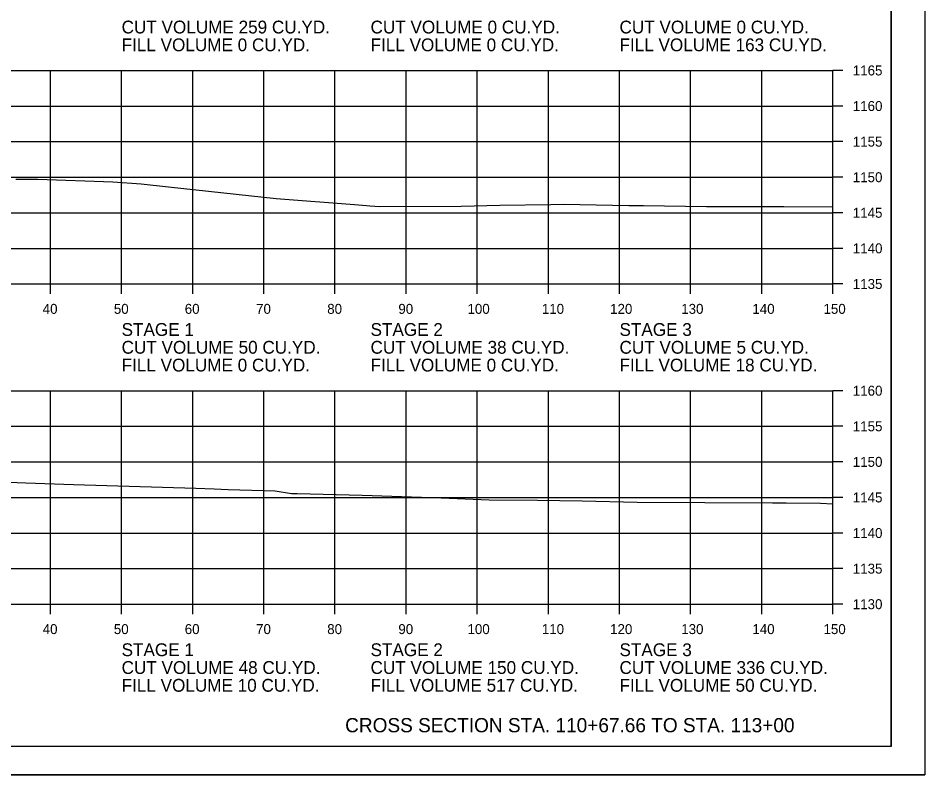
# Model space of a CAD drawing. Extents: x 1368971 to 1374497, y 378717 to 381839.
# Drawn here: x 1371088.2 to 1371215.6, y 379783.8 to 379890.1 of the extents above; entities that cross this region are included whole.
import ezdxf

# ---------------------------------------------------------------- set-up
doc = ezdxf.new("R2010")
doc.units = 0
for name, color, linetype in [('R_Axis', 7, 'Continuous'), ('R_Axis Annot', 7, 'Continuous'), ('R_Border', 7, 'Continuous'), ('R_Draft', 7, 'Continuous'), ('R_Exist Surface', 7, 'Continuous'), ('R_Grid', 7, 'Continuous'), ('R_No Plot', 7, 'Continuous')]:
    doc.layers.add(name, color=color, linetype=linetype)

msp = doc.modelspace()

# ---------------------------------------------------------------- linework, layer by layer
at = {"layer": 'R_Axis'}
for p, q in [((1371202.71, 379852.75), (1371202.71, 379882.75)), ((1371204.11, 379882.75), (1371202.71, 379882.75)), ((1371204.11, 379877.75), (1371202.71, 379877.75)), ((1371204.11, 379872.75), (1371202.71, 379872.75)), ((1371204.11, 379867.75), (1371202.71, 379867.75)), ((1371204.11, 379862.75), (1371202.71, 379862.75)), ((1371204.11, 379857.75), (1371202.71, 379857.75)), ((1370902.71, 379852.75), (1371202.71, 379852.75)), ((1371092.71, 379851.35), (1371092.71, 379852.75)), ((1371102.71, 379851.35), (1371102.71, 379852.75)), ((1371112.71, 379851.35), (1371112.71, 379852.75)), ((1371122.71, 379851.35), (1371122.71, 379852.75)), ((1371132.71, 379851.35), (1371132.71, 379852.75)), ((1371142.71, 379851.35), (1371142.71, 379852.75)), ((1371152.71, 379851.35), (1371152.71, 379852.75)), ((1371162.71, 379851.35), (1371162.71, 379852.75)), ((1371172.71, 379851.35), (1371172.71, 379852.75)), ((1371182.71, 379851.35), (1371182.71, 379852.75)), ((1371192.71, 379851.35), (1371192.71, 379852.75)), ((1371202.71, 379851.35), (1371202.71, 379852.75)), ((1371204.11, 379852.75), (1371202.71, 379852.75)), ((1371202.71, 379807.75), (1371202.71, 379837.75)), ((1371204.11, 379837.75), (1371202.71, 379837.75)), ((1371204.11, 379832.75), (1371202.71, 379832.75)), ((1371204.11, 379827.75), (1371202.71, 379827.75)), ((1371204.11, 379822.75), (1371202.71, 379822.75)), ((1371204.11, 379817.75), (1371202.71, 379817.75)), ((1371204.11, 379812.75), (1371202.71, 379812.75)), ((1370902.71, 379807.75), (1371202.71, 379807.75)), ((1371092.71, 379806.35), (1371092.71, 379807.75)), ((1371102.71, 379806.35), (1371102.71, 379807.75)), ((1371112.71, 379806.35), (1371112.71, 379807.75)), ((1371122.71, 379806.35), (1371122.71, 379807.75)), ((1371132.71, 379806.35), (1371132.71, 379807.75)), ((1371142.71, 379806.35), (1371142.71, 379807.75)), ((1371152.71, 379806.35), (1371152.71, 379807.75)), ((1371162.71, 379806.35), (1371162.71, 379807.75)), ((1371172.71, 379806.35), (1371172.71, 379807.75)), ((1371182.71, 379806.35), (1371182.71, 379807.75)), ((1371192.71, 379806.35), (1371192.71, 379807.75)), ((1371202.71, 379806.35), (1371202.71, 379807.75)), ((1371204.11, 379807.75), (1371202.71, 379807.75))]:
    msp.add_line(p, q, dxfattribs=at)
at = {"layer": 'R_Border'}
for q in [(1371210.89, 379993.21), (1370894.71, 379787.75)]:
    msp.add_line((1371210.89, 379787.75), q, dxfattribs=at)
at = {"layer": 'R_Exist Surface'}
for points in [[(1371087.83, 379867.46), (1371090.94, 379867.49), (1371101.5, 379867.09), (1371105.45, 379866.83), (1371109.29, 379866.42), (1371124.46, 379864.76), (1371135.45, 379863.9), (1371137.14, 379863.78), (1371137.59, 379863.74), (1371139.02, 379863.62), (1371150.46, 379863.69), (1371155.87, 379863.8), (1371163.06, 379863.93), (1371164.82, 379863.96), (1371174, 379863.79), (1371176.07, 379863.78), (1371184.92, 379863.64), (1371189.5, 379863.62), (1371195.82, 379863.62), (1371202.71, 379863.6)], [(1371080.6, 379825.12), (1371089.26, 379824.82), (1371095.96, 379824.58), (1371113.13, 379824.04), (1371115.74, 379823.95), (1371117.67, 379823.89), (1371124.28, 379823.69), (1371126.59, 379823.32), (1371127.39, 379823.29), (1371136.51, 379823.05), (1371147.63, 379822.69), (1371154.4, 379822.42), (1371161.17, 379822.35), (1371167.47, 379822.26), (1371175.2, 379822.08), (1371194.24, 379821.98), (1371196.14, 379821.98), (1371200.98, 379821.95), (1371202.71, 379821.87)]]:
    msp.add_lwpolyline(points, dxfattribs=at)
at = {"layer": 'R_Grid'}
for p, q in [((1370902.71, 379882.75), (1371202.71, 379882.75)), ((1371092.71, 379852.75), (1371092.71, 379882.75)), ((1371102.71, 379852.75), (1371102.71, 379882.75)), ((1371112.71, 379852.75), (1371112.71, 379882.75)), ((1371122.71, 379852.75), (1371122.71, 379882.75)), ((1371132.71, 379852.75), (1371132.71, 379882.75)), ((1371142.71, 379852.75), (1371142.71, 379882.75)), ((1371152.71, 379852.75), (1371152.71, 379882.75)), ((1371162.71, 379852.75), (1371162.71, 379882.75)), ((1371172.71, 379852.75), (1371172.71, 379882.75)), ((1371182.71, 379852.75), (1371182.71, 379882.75)), ((1371192.71, 379852.75), (1371192.71, 379882.75)), ((1371202.71, 379852.75), (1371202.71, 379882.75)), ((1370902.71, 379877.75), (1371202.71, 379877.75)), ((1370902.71, 379872.75), (1371202.71, 379872.75)), ((1370902.71, 379867.75), (1371202.71, 379867.75)), ((1370902.71, 379862.75), (1371202.71, 379862.75)), ((1370902.71, 379857.75), (1371202.71, 379857.75)), ((1370902.71, 379852.75), (1371202.71, 379852.75)), ((1370902.71, 379837.75), (1371202.71, 379837.75)), ((1371092.71, 379807.75), (1371092.71, 379837.75)), ((1371102.71, 379807.75), (1371102.71, 379837.75)), ((1371112.71, 379807.75), (1371112.71, 379837.75)), ((1371122.71, 379807.75), (1371122.71, 379837.75)), ((1371132.71, 379807.75), (1371132.71, 379837.75)), ((1371142.71, 379807.75), (1371142.71, 379837.75)), ((1371152.71, 379807.75), (1371152.71, 379837.75)), ((1371162.71, 379807.75), (1371162.71, 379837.75)), ((1371172.71, 379807.75), (1371172.71, 379837.75)), ((1371182.71, 379807.75), (1371182.71, 379837.75)), ((1371192.71, 379807.75), (1371192.71, 379837.75)), ((1371202.71, 379807.75), (1371202.71, 379837.75)), ((1370902.71, 379832.75), (1371202.71, 379832.75)), ((1370902.71, 379827.75), (1371202.71, 379827.75)), ((1370902.71, 379822.75), (1371202.71, 379822.75)), ((1370902.71, 379817.75), (1371202.71, 379817.75)), ((1370902.71, 379812.75), (1371202.71, 379812.75)), ((1370902.71, 379807.75), (1371202.71, 379807.75))]:
    msp.add_line(p, q, dxfattribs=at)
at = {"layer": 'R_No Plot'}
msp.add_line((1370882.31, 379783.77), (1371215.64, 379783.77), dxfattribs=at)
for points in [[(1370882.3, 379997.11), (1371215.64, 379997.11), (1371215.64, 379783.77), (1370882.3, 379783.77)], [(1371128.63, 379993.21), (1371128.63, 379983.33), (1371164.36, 379983.33), (1371164.36, 379980.41), (1371187.56, 379980.41), (1371187.56, 379956.08), (1371210.89, 379956.08), (1371210.89, 379787.75), (1370894.71, 379787.75), (1370894.71, 379993.21)]]:
    msp.add_lwpolyline(points, close=True, dxfattribs=at)

# ---------------------------------------------------------------- texts
at = {"layer": 'R_Axis Annot'}
for s, height, p in [('CUT VOLUME 259 CU.YD.', 1.8, (1371102.71, 379887.95)), ('CUT VOLUME 0 CU.YD.', 1.8, (1371137.71, 379887.95)), ('CUT VOLUME 0 CU.YD.', 1.8, (1371172.71, 379887.95)), ('FILL VOLUME 0 CU.YD.', 1.8, (1371102.71, 379885.45)), ('FILL VOLUME 0 CU.YD.', 1.8, (1371137.71, 379885.45)), ('FILL VOLUME 163 CU.YD.', 1.8, (1371172.71, 379885.45)), ('1165', 1.4, (1371205.51, 379882.05)), ('1160', 1.4, (1371205.51, 379877.05)), ('1155', 1.4, (1371205.51, 379872.05)), ('1150', 1.4, (1371205.51, 379867.05)), ('1145', 1.4, (1371205.51, 379862.05)), ('1140', 1.4, (1371205.51, 379857.05)), ('1135', 1.4, (1371205.51, 379852.05)), ('40', 1.4, (1371091.62, 379848.55)), ('50', 1.4, (1371101.62, 379848.55)), ('60', 1.4, (1371111.59, 379848.55)), ('70', 1.4, (1371121.62, 379848.55)), ('80', 1.4, (1371131.62, 379848.55)), ('90', 1.4, (1371141.62, 379848.55)), ('100', 1.4, (1371151.34, 379848.55)), ('110', 1.4, (1371161.79, 379848.55)), ('120', 1.4, (1371171.39, 379848.55)), ('130', 1.4, (1371181.39, 379848.55)), ('140', 1.4, (1371191.39, 379848.55)), ('150', 1.4, (1371201.39, 379848.55)), ('STAGE 1', 1.8, (1371102.71, 379845.45)), ('STAGE 2', 1.8, (1371137.71, 379845.45)), ('STAGE 3', 1.8, (1371172.71, 379845.45)), ('CUT VOLUME 50 CU.YD.', 1.8, (1371102.71, 379842.95)), ('CUT VOLUME 38 CU.YD.', 1.8, (1371137.71, 379842.95)), ('CUT VOLUME 5 CU.YD.', 1.8, (1371172.71, 379842.95)), ('FILL VOLUME 0 CU.YD.', 1.8, (1371102.71, 379840.45)), ('FILL VOLUME 0 CU.YD.', 1.8, (1371137.71, 379840.45)), ('FILL VOLUME 18 CU.YD.', 1.8, (1371172.71, 379840.45)), ('1160', 1.4, (1371205.51, 379837.05)), ('1155', 1.4, (1371205.51, 379832.05)), ('1150', 1.4, (1371205.51, 379827.05)), ('1145', 1.4, (1371205.51, 379822.05)), ('1140', 1.4, (1371205.51, 379817.05)), ('1135', 1.4, (1371205.51, 379812.05)), ('1130', 1.4, (1371205.51, 379807.05)), ('40', 1.4, (1371091.62, 379803.55)), ('50', 1.4, (1371101.62, 379803.55)), ('60', 1.4, (1371111.59, 379803.55)), ('70', 1.4, (1371121.62, 379803.55)), ('80', 1.4, (1371131.62, 379803.55)), ('90', 1.4, (1371141.62, 379803.55)), ('100', 1.4, (1371151.34, 379803.55)), ('110', 1.4, (1371161.79, 379803.55)), ('120', 1.4, (1371171.39, 379803.55)), ('130', 1.4, (1371181.39, 379803.55)), ('140', 1.4, (1371191.39, 379803.55)), ('150', 1.4, (1371201.39, 379803.55)), ('STAGE 1', 1.8, (1371102.71, 379800.45)), ('STAGE 2', 1.8, (1371137.71, 379800.45)), ('STAGE 3', 1.8, (1371172.71, 379800.45)), ('CUT VOLUME 48 CU.YD.', 1.8, (1371102.71, 379797.95)), ('CUT VOLUME 150 CU.YD.', 1.8, (1371137.71, 379797.95)), ('CUT VOLUME 336 CU.YD.', 1.8, (1371172.71, 379797.95)), ('FILL VOLUME 10 CU.YD.', 1.8, (1371102.71, 379795.45)), ('FILL VOLUME 517 CU.YD.', 1.8, (1371137.71, 379795.45)), ('FILL VOLUME 50 CU.YD.', 1.8, (1371172.71, 379795.45))]:
    msp.add_text(s, height=height, dxfattribs=at).set_placement(p)
at = {"layer": 'R_Draft'}
msp.add_text('CROSS SECTION STA. 110+67.66 TO STA. 113+00', height=2, dxfattribs=at).set_placement((1371134.14, 379789.75))

doc.saveas('drawing.dxf')
